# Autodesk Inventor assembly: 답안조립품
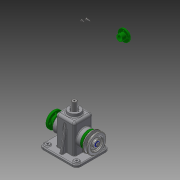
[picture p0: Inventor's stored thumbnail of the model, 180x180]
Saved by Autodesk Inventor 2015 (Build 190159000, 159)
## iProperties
Created: 2016-02
Part Number: 답안조립품
Document SubType Name: Assembly
Designer: Administrator
Author: Administrator
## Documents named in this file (19)
- C:\Users\Administrator\Desktop\460219V1013\답안조립품.iam
- C:\Users\Administrator\Desktop\460219V1013\본체.ipt
- C:\Users\Administrator\Desktop\460219V1013\V-벨트풀리.ipt
- C:\Users\Administrator\Desktop\460219V1013\고정핀.ipt
- C:\Users\Administrator\Desktop\460219V1013\뒤커버.ipt
- C:\Users\Administrator\Desktop\460219V1013\링크.ipt
- C:\Users\Administrator\Desktop\460219V1013\멈춤링 6 x 5.ipt
- C:\Users\Administrator\Desktop\460219V1013\멈춤링 15 x 1.ipt
- C:\Users\Administrator\Desktop\460219V1013\베어링 15 x 35 x 11.ipt
- C:\Users\Administrator\Desktop\460219V1013\볼트 M3 x 8.ipt
- C:\Users\Administrator\Desktop\460219V1013\볼트 M4 x 10.ipt
- C:\Users\Administrator\Desktop\460219V1013\볼트 M6 x 12.ipt
- C:\Users\Administrator\Desktop\460219V1013\상부부시.ipt
- C:\Users\Administrator\Desktop\460219V1013\슬라이드바.ipt
- C:\Users\Administrator\Desktop\460219V1013\앞커버.ipt
- C:\Users\Administrator\Desktop\460219V1013\오일실 15 25 7.ipt
- C:\Users\Administrator\Desktop\460219V1013\와셔.ipt
- C:\Users\Administrator\Desktop\460219V1013\키 5 x 5 x 14.ipt
- C:\Users\Administrator\Desktop\460219V1013\편심축.ipt
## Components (5 placed, 5 different names)
1. V-벨트풀리:1
2. 고정핀:1
3. ISO 4762 M3 x 8:1
4. ISO 4762 M4 x 10:1
5. ISO 4018 M6 x 12:1
